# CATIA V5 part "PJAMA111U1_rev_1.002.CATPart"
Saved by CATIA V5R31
Part number: JAMA111U1
Revision: 1
Nomenclature: SEAT_ANC_LH
Source: Unknown
Property "部品番号(A社)": "JAMA111U1"
Property "部品名称(A社)": "SEAT_ANC_LH"
Property "Version(A社)": "1"
Property "材質(A社)": "SS400B"
Bounding box of the stored display mesh (mm): x 4086.42 to 4141.807, y -534.757 to -476.307, z 624.356 to 661.826
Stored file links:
  \\solize.local\damia\dept\DDE_Design\10_order\2305701_JAMA_変換検証STEP3_お手本モデル作成\work\02_マツダ_板金\10_CATIA_V5\231211\PJAMA111U1_rev_1.002.CATPart
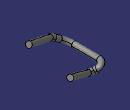
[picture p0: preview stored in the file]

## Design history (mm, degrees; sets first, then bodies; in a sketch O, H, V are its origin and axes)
f4a2d38f3ddc11d3a929006094b99c4b_11 "CATTPSSet"
TTRSSet1
Body1 "MANIFOLD_SOLID_BREP #9752" (main body)
  Solid1: solid without history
